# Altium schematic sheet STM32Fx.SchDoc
size A4; DocumentNumber: 3; Revision: D.1(PCB.SCH); SheetNumber: 3; SheetTotal: 6
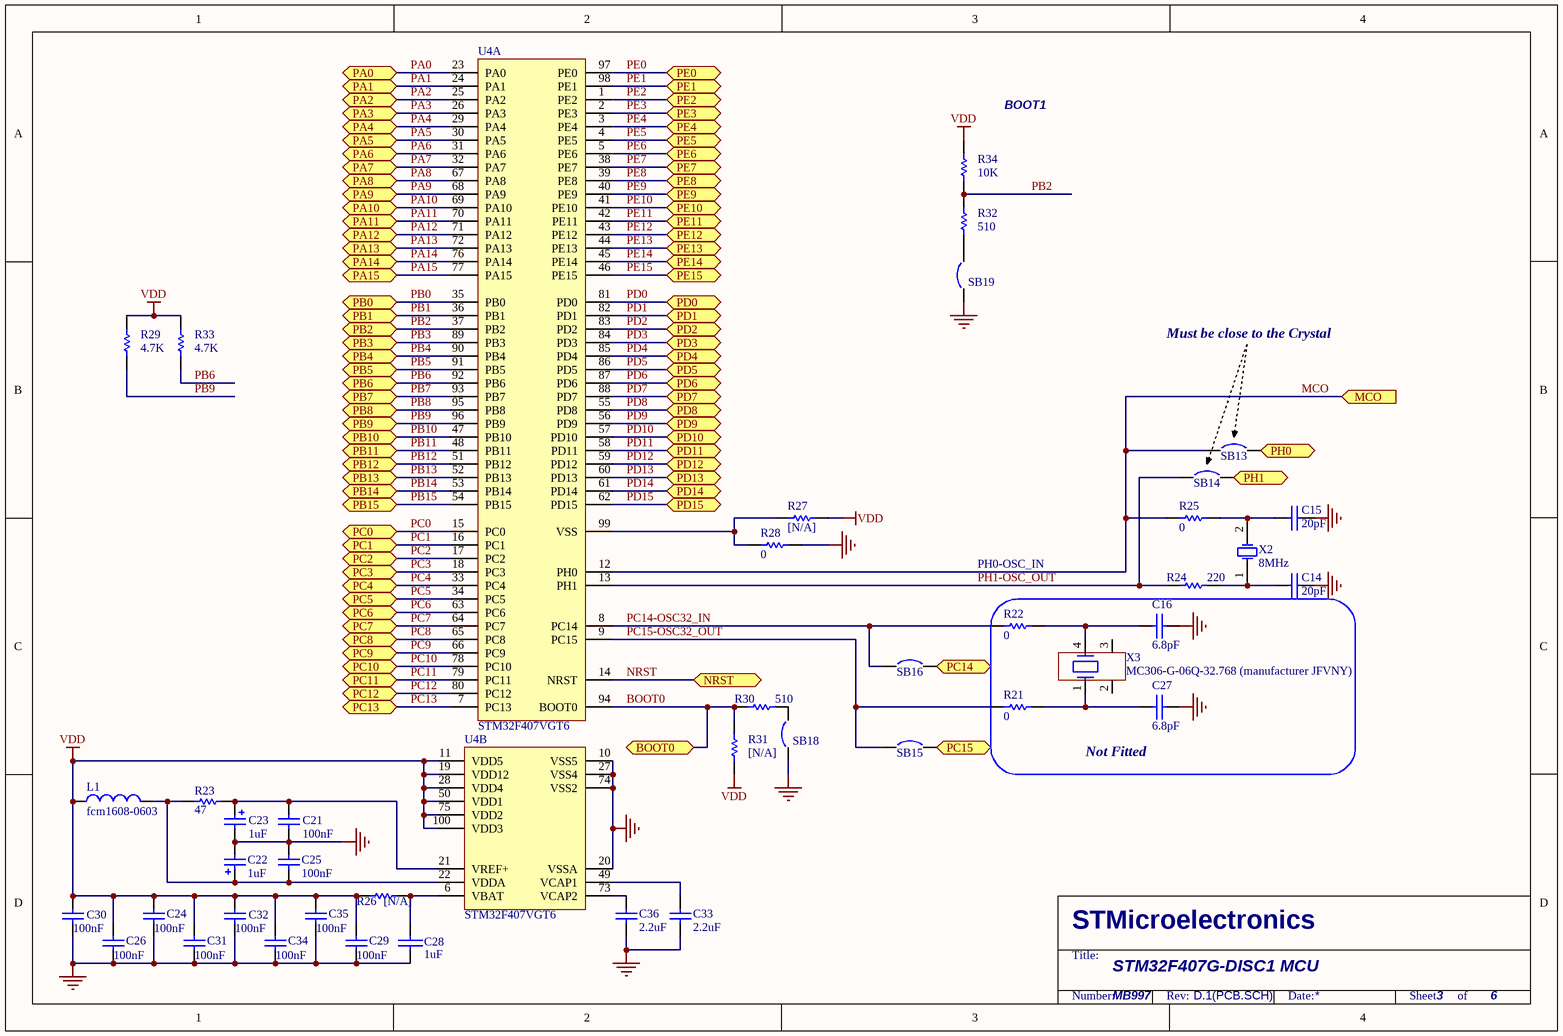
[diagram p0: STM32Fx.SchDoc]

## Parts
C14  20pF  [0603C]
C15  20pF  [0603C]
C16  6.8pF  [0603C]
C21  100nF  [0603C]
C22  1uF  [CASE-AA]
C23  1uF  [CASE-AA]
C24  100nF  [0603C]
C25  100nF  [0603C]
C26  100nF  [0603C]
C27  6.8pF  [0603C]
C28  1uF  [0603C]
C29  100nF  [0603C]
C30  100nF  [0603C]
C31  100nF  [0603C]
C32  100nF  [0603C]
C33  2.2uF  [CASE-A]
C34  100nF  [0603C]
C35  100nF  [0603C]
C36  2.2uF  [CASE-A]
L1  fcm1608-0603  [0603L]
R21  0  [0603R]
R22  0  [0603R]
R23  47  [0603R]
R24  220  [0603R]
R25  0  [0603R]
R26  [N/A]  [0603R]
R27  [N/A]  [0603R]
R28  0  [0603R]
R29  4.7K  [0402R]
R30  510  [0603R]
R31  [N/A]  [0402R]
R32  510  [0603R]
R33  4.7K  [0402R]
R34  10K  [0402R]
SB13  Circuit Breaker  [JP2_SMD]  (value not drawn)
SB14  Circuit Breaker  [JP2_SMD]  (value not drawn)
SB15  Circuit Breaker  [JP2_SMD]  (value not drawn)
SB16  Circuit Breaker  [JP2_SMD]  (value not drawn)
SB18  Circuit Breaker  [JP2_SMD]  (value not drawn)
SB19  Circuit Breaker  [JP2_SMD]  (value not drawn)
U4  STM32F407VGT6  [TQFP100]  (parts A,B of 2)
X2  8MHz  [XTAL1]
X3  MC306-G-06Q-32.768 (manufacturer JFVNY)  [MC306-CRYSTAL]

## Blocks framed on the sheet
Not Fitted: C16 C27 R21 R22 X3

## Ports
BOOT0, MCO (in), NRST, PA0 (bidir), PA1 (bidir), PA2 (bidir), PA3 (bidir), PA4 (bidir), PA5 (bidir), PA6 (bidir), PA7 (bidir), PA8 (bidir), PA9 (bidir), PA10 (bidir), PA11 (bidir), PA12 (bidir), PA13 (bidir), PA14 (bidir), PA15 (bidir), PB0 (bidir), PB1 (bidir), PB2 (bidir), PB3 (bidir), PB4 (bidir), PB5 (bidir), PB6 (bidir), PB7 (bidir), PB8 (bidir), PB9 (bidir), PB10 (bidir), PB11 (bidir), PB12 (bidir), PB13 (bidir), PB14 (bidir), PB15 (bidir), PC0 (bidir), PC1 (bidir), PC2 (bidir), PC3 (bidir), PC4 (bidir), PC5 (bidir), PC6 (bidir), PC7 (bidir), PC8 (bidir), PC9 (bidir), PC10 (bidir), PC11 (bidir), PC12 (bidir), PC13 (bidir), PC14 (bidir), PC15 (bidir), PD0, PD1, PD2, PD3, PD4, PD5, PD6, PD7, PD8, PD9, PD10, PD11, PD12, PD13, PD14, PD15, PE0, PE1, PE2, PE3, PE4, PE5, PE6, PE7, PE8, PE9, PE10, PE11, PE12, PE13, PE14, PE15, PH0, PH1

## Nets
GND: C14.1 C15.1 C16.2 C21.1 C22.2 C23.2 C24.2 C25.1 C26.1 C27.2 C28.2 C29.1 C30.1 C31.1 C32.1 C33.2 C34.1 C35.2 C36.2 R28.2 SB18.1 SB19.1 U4.10(VSS5) U4.20(VSSA) U4.27(VSS4) U4.74(VSS2)
VDD: C24.1 C26.2 C29.2 C30.2 C31.2 C32.2 C34.2 C35.1 L1.1 R26.1 R27.2 R29.1 R31.2 R33.1 R34.1 U4.11(VDD5) U4.19(VDD12) U4.28(VDD4) U4.50(VDD1) U4.75(VDD2) U4.100(VDD3)
BOOT0: R30.2 R31.1 U4.94(BOOT0) ; port BOOT0
MCO: R25.1 SB13.1 U4.12(PH0) ; port MCO
NRST: U4.14(NRST) ; port NRST
PA0: U4.23(PA0) ; port PA0
PA1: U4.24(PA1) ; port PA1
PA2: U4.25(PA2) ; port PA2
PA3: U4.26(PA3) ; port PA3
PA4: U4.29(PA4) ; port PA4
PA5: U4.30(PA5) ; port PA5
PA6: U4.31(PA6) ; port PA6
PA7: U4.32(PA7) ; port PA7
PA8: U4.67(PA8) ; port PA8
PA9: U4.68(PA9) ; port PA9
PA10: U4.69(PA10) ; port PA10
PA11: U4.70(PA11) ; port PA11
PA12: U4.71(PA12) ; port PA12
PA13: U4.72(PA13) ; port PA13
PA14: U4.76(PA14) ; port PA14
PA15: U4.77(PA15) ; port PA15
PB0: U4.35(PB0) ; port PB0
PB1: U4.36(PB1) ; port PB1
PB2: R32.1 R34.2 U4.37(PB2) ; port PB2
PB3: U4.89(PB3) ; port PB3
PB4: U4.90(PB4) ; port PB4
PB5: U4.91(PB5) ; port PB5
PB6: R33.2 U4.92(PB6) ; port PB6
PB7: U4.93(PB7) ; port PB7
PB8: U4.95(PB8) ; port PB8
PB9: R29.2 U4.96(PB9) ; port PB9
PB10: U4.47(PB10) ; port PB10
PB11: U4.48(PB11) ; port PB11
PB12: U4.51(PB12) ; port PB12
PB13: U4.52(PB13) ; port PB13
PB14: U4.53(PB14) ; port PB14
PB15: U4.54(PB15) ; port PB15
PC0: U4.15(PC0) ; port PC0
PC1: U4.16(PC1) ; port PC1
PC2: U4.17(PC2) ; port PC2
PC3: U4.18(PC3) ; port PC3
PC4: U4.33(PC4) ; port PC4
PC5: U4.34(PC5) ; port PC5
PC6: U4.63(PC6) ; port PC6
PC7: U4.64(PC7) ; port PC7
PC8: U4.65(PC8) ; port PC8
PC9: U4.66(PC9) ; port PC9
PC10: U4.78(PC10) ; port PC10
PC11: U4.79(PC11) ; port PC11
PC12: U4.80(PC12) ; port PC12
PC13: U4.7(PC13) ; port PC13
PC14: SB16.2 ; port PC14
PC14-OSC32_IN: R22.1 SB16.1 U4.8(PC14)
PC15: SB15.2 ; port PC15
PC15-OSC32_OUT: R21.1 SB15.1 U4.9(PC15)
PD0: U4.81(PD0) ; port PD0
PD1: U4.82(PD1) ; port PD1
PD2: U4.83(PD2) ; port PD2
PD3: U4.84(PD3) ; port PD3
PD4: U4.85(PD4) ; port PD4
PD5: U4.86(PD5) ; port PD5
PD6: U4.87(PD6) ; port PD6
PD7: U4.88(PD7) ; port PD7
PD8: U4.55(PD8) ; port PD8
PD9: U4.56(PD9) ; port PD9
PD10: U4.57(PD10) ; port PD10
PD11: U4.58(PD11) ; port PD11
PD12: U4.59(PD12) ; port PD12
PD13: U4.60(PD13) ; port PD13
PD14: U4.61(PD14) ; port PD14
PD15: U4.62(PD15) ; port PD15
PE0: U4.97(PE0) ; port PE0
PE1: U4.98(PE1) ; port PE1
PE2: U4.1(PE2) ; port PE2
PE3: U4.2(PE3) ; port PE3
PE4: U4.3(PE4) ; port PE4
PE5: U4.4(PE5) ; port PE5
PE6: U4.5(PE6) ; port PE6
PE7: U4.38(PE7) ; port PE7
PE8: U4.39(PE8) ; port PE8
PE9: U4.40(PE9) ; port PE9
PE10: U4.41(PE10) ; port PE10
PE11: U4.42(PE11) ; port PE11
PE12: U4.43(PE12) ; port PE12
PE13: U4.44(PE13) ; port PE13
PE14: U4.45(PE14) ; port PE14
PE15: U4.46(PE15) ; port PE15
PH0: SB13.2 ; port PH0
PH1: SB14.2 ; port PH1
PH1-OSC_OUT: R24.2 SB14.1 U4.13(PH1)
NetC14_2: C14.2 R24.1 X2.1(OSC1)
NetC15_2: C15.2 R25.2 X2.2(OSC2)
NetC16_1: C16.1 R22.2 X3.4
NetC21_2: C21.2 C23.1 R23.1 U4.21(VREF+)
NetC22_1: C22.1 C25.2 L1.2 R23.2 U4.22(VDDA)
NetC27_1: C27.1 R21.2 X3.1
NetC28_1: C28.1 R26.2 U4.6(VBAT)
NetC33_1: C33.1 U4.49(VCAP1)
NetC36_1: C36.1 U4.73(VCAP2)
NetR27_1: R27.1 R28.1 U4.99(VSS)
NetR30_1: R30.1 SB18.2
NetR32_2: R32.2 SB19.2

Not connected (* = marked no-connect by the designer): X3 2 3

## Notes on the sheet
- BOOT1
- Must be close to the Crystal
- PH0-OSC_IN
- STM32F407G-DISC1 MCU
- MB997

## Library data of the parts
C14 C15 C28 = CAP: Capacitor
C16 C27 = CAP: Capacitor; Fitted: NO
C21 C24-C26 C29-C32 C34 C35 = Cap: Capacitor
C22 C23 = Cap Pol1: Polarized Capacitor (Radial); Value: 10uF
C33 C36 = Cap Low ESR: Low ESR Ceramic Capacitor (X7R); Order: CC1206KKX7R7BB225
L1 = Inductor: Value: 100uH
R21 R22 R25 = Res1: Resistor; Fitted: NO
R23 = Res1: Resistor; Value: 1K
R24 R28 R30 = Res1: Resistor
R26 = res1: Resistor; Value: 0; Fitted: NO
R27 = Res1: Resistor; Value: 0; Fitted: NO
R29 R33 = res1: Resistor; Value: 10K
R31 = res1: Resistor; Value: 10K; Fitted: NO
R32 R34 = res1: Resistor
SB13 SB15 SB16 SB19 = Circuit Breaker: Solder: NO
SB14 SB18 = Circuit Breaker: Solder: YES
U4 = STM32F407VGT6: STM32 Manta (STM32F407VGT6); Manuf_1: STM; Provided: ST; Ref St: 9175122; ECCN_US/EU: 3A991A2/NEC
X2 = XTAL: Crystal Oscillator
X3 = MC306: Fitted: NO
